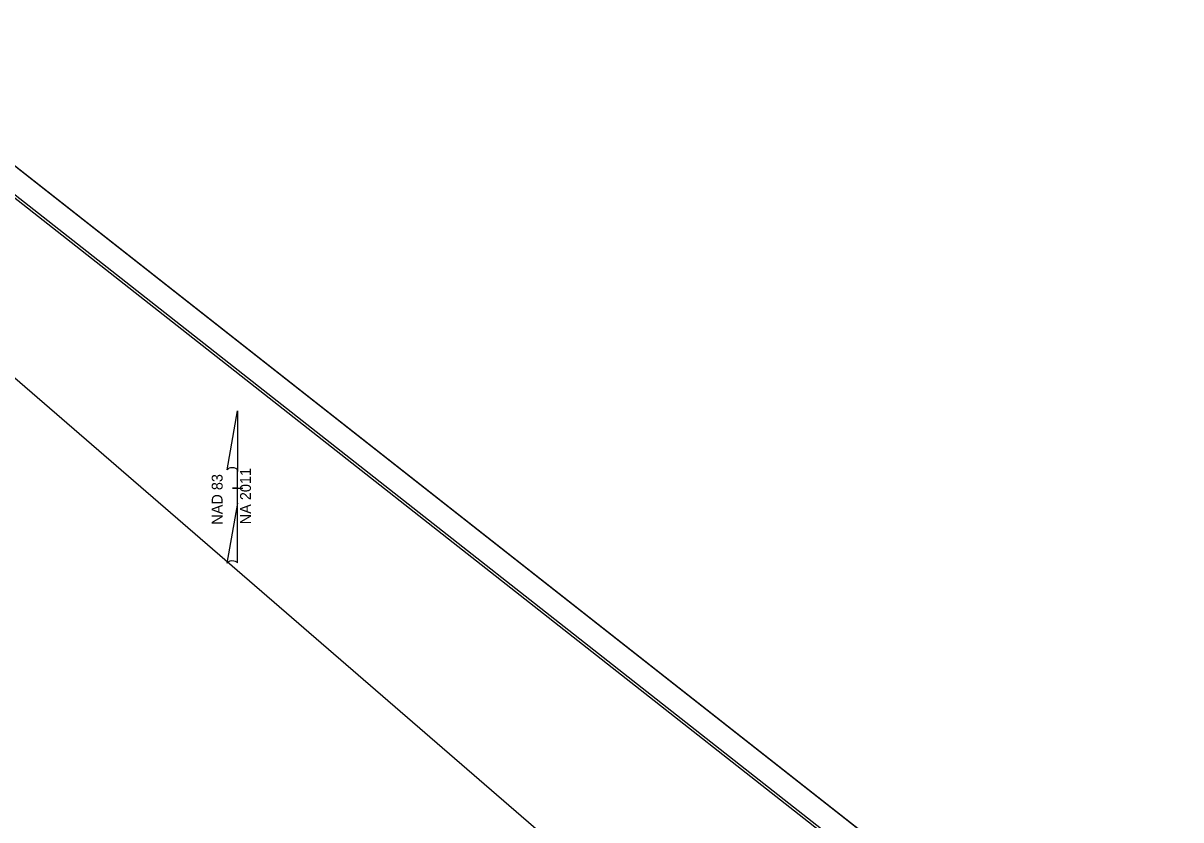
# Model space of a CAD drawing. Extents: x 556999 to 560450, y 504801 to 507732.
# Drawn here: x 557693 to 558602, y 507105 to 507732 of the extents above; entities that cross this region are included whole.
import ezdxf

# ---------------------------------------------------------------- set-up
doc = ezdxf.new("R2010")
doc.units = 0
for name, color, linetype in [('Prop Horizontal Alignment Station Label', 7, 'Continuous'), ('Sheet Border Standard 30in CELL', 7, 'Continuous'), ('Sheet Clip Boundary CELL', 7, 'Continuous'), ('Sheet Cutting Line CELL', 7, 'Continuous'), ('Sheet Plot Border Inside CELL', 7, 'Continuous'), ('Sheet Plot Border Outside CELL', 7, 'Continuous')]:
    doc.layers.add(name, color=color, linetype=linetype)

msp = doc.modelspace()

# ---------------------------------------------------------------- linework, layer by layer
at = {"layer": 'Prop Horizontal Alignment Station Label'}
for p, q in [((557852.71, 507380.58), (557860.91, 507426.93)), ((557860.96, 507426.93), (557860.91, 507426.93)), ((557860.96, 507426.93), (557860.91, 507426.93)), ((557860.96, 507426.93), (557860.96, 507379.13)), ((557860.96, 507354.33), (557860.96, 507380.53)), ((557860.96, 507379.13), (557860.96, 507380.48)), ((557856.96, 507365.93), (557856.91, 507365.93)), ((557860.51, 507365.93), (557856.96, 507365.93)), ((557857.01, 507365.93), (557865.01, 507365.93)), ((557860.96, 507354.33), (557852.61, 507307.08)), ((557861.01, 507307.28), (557860.96, 507354.33))]:
    msp.add_line(p, q, dxfattribs=at)
for centre, start_param, end_param in [((557856.85, 507380.08), 0.216388, 2.908219), ((557856.85, 507306.91), 0.201328, 3.141593)]:
    msp.add_ellipse(centre, major_axis=(4.23, -0.03), ratio=0.461098, start_param=start_param, end_param=end_param, dxfattribs=at)
at = {"layer": 'Sheet Border Standard 30in CELL'}
msp.add_lwpolyline([(558579, 506891.48), (557635.74, 507633.27), (557116.49, 506972.99), (558059.75, 506231.2)], close=True, dxfattribs=at)
at = {"layer": 'Sheet Clip Boundary CELL'}
msp.add_lwpolyline([(557670.21, 507466.23), (558103.06, 507091.75), (558010.57, 506993.11), (557957.23, 506919.09), (557959.37, 506915.73), (557924.17, 506870.66), (557915.94, 506859.67), (557912.12, 506855.15), (557904.86, 506850.09), (557847.72, 506801.46), (557761.69, 506715.56), (557751.89, 506695.94), (557782.23, 506664.04), (557786.18, 506640.54), (557672.55, 506724.62), (557610.32, 506776.93), (557401.38, 506939.59), (557410.24, 506997.06), (557374.28, 507190.56)], close=True, dxfattribs=at)
at = {"layer": 'Sheet Cutting Line CELL'}
msp.add_line((558602.06, 506898.8), (557543.09, 507731.58), dxfattribs=at)
at = {"layer": 'Sheet Plot Border Inside CELL'}
msp.add_lwpolyline([(558588.12, 506886.9), (557540.16, 507711.03), (557018.38, 507047.54), (558066.35, 506223.41)], close=True, dxfattribs=at)
at = {"layer": 'Sheet Plot Border Outside CELL'}
msp.add_lwpolyline([(558602.06, 506898.8), (557543.09, 507731.58), (556999.11, 507039.85), (558058.08, 506207.07)], close=True, dxfattribs=at)

# ---------------------------------------------------------------- texts
at = {"layer": 'Prop Horizontal Alignment Station Label'}
for s, p in [('NA 2011', (557871.48, 507337.65)), ('NAD 83', (557849.19, 507337.32))]:
    msp.add_text(s, height=8.5, rotation=90, dxfattribs=at).set_placement(p)

doc.saveas('drawing.dxf')
